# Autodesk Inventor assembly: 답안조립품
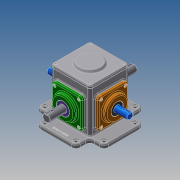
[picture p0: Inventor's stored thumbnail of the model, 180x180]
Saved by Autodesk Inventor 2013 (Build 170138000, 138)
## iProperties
Created: 2019-12
Part Number: 답안조립품
Document SubType Name: Assembly
Designer: Administrator
Mass: 3483.74 g
Surface Area: 3365.09 cm^2
Volume: 1062.39 cm^3
Density: 3.27916 g/cm^3
Author: Administrator
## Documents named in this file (16)
- C:\Users\Administrator\Desktop\391204V1030\답안조립품.iam
- C:\Users\Administrator\Desktop\391204V1030\개스킷.ipt
- C:\Users\Administrator\Desktop\391204V1030\메인베벨기어.ipt
- C:\Users\Administrator\Desktop\391204V1030\메인축.ipt
- C:\Users\Administrator\Desktop\391204V1030\메인커버.ipt
- C:\Users\Administrator\Desktop\391204V1030\베어링 6203.ipt
- C:\Users\Administrator\Desktop\391204V1030\베어링 6204.ipt
- C:\Users\Administrator\Desktop\391204V1030\본체.ipt
- C:\Users\Administrator\Desktop\391204V1030\볼트 M4.ipt
- C:\Users\Administrator\Desktop\391204V1030\상부커버.ipt
- C:\Users\Administrator\Desktop\391204V1030\서브베벨기어.ipt
- C:\Users\Administrator\Desktop\391204V1030\서브축.ipt
- C:\Users\Administrator\Desktop\391204V1030\서브커버.ipt
- C:\Users\Administrator\Desktop\391204V1030\오일 실 17 32 8.ipt
- C:\Users\Administrator\Desktop\391204V1030\오일 실 20 35 8.ipt
- C:\Users\Administrator\Desktop\391204V1030\키 4x4.ipt
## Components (1 placed, 1 different names)
1. 개스킷:1
